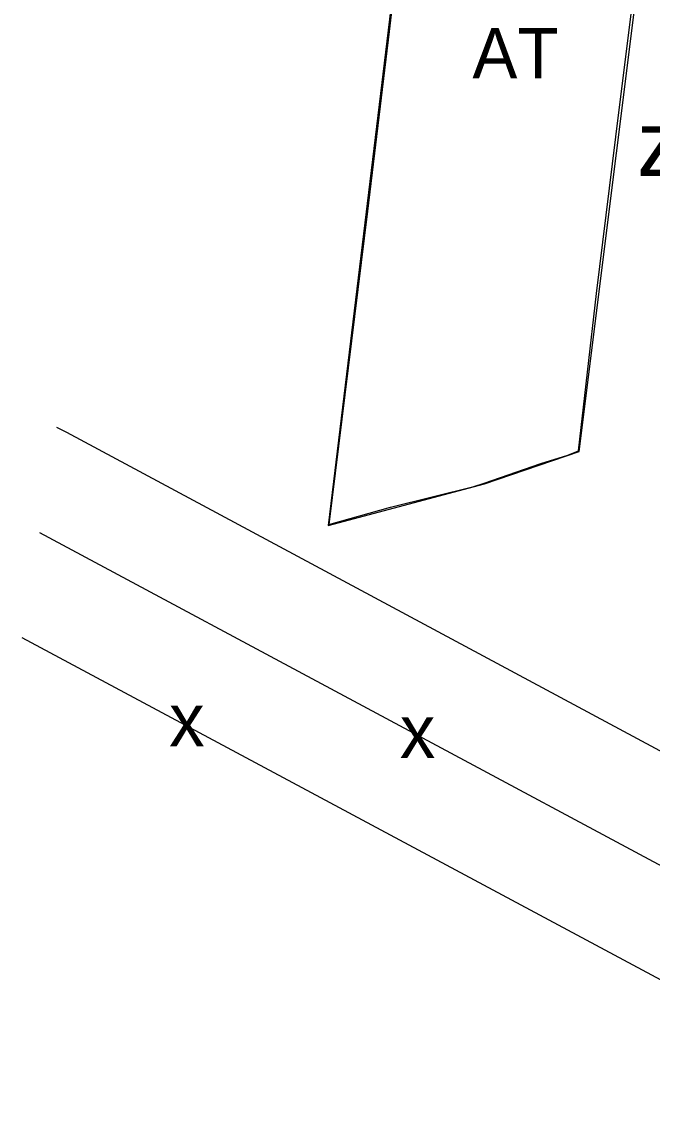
# Model space of a CAD drawing. Extents: x -555070 to -553076, y -1186731 to -1182766.
# Drawn here: x -555070.2 to -554895.6, y -1185500.5 to -1185196 of the extents above; entities that cross this region are included whole.
import ezdxf

# ---------------------------------------------------------------- set-up
doc = ezdxf.new("R2010")
doc.units = 0
for name, color, linetype in [('HRANICE_ZMENY_DO_KOO', 7, 'Continuous'), ('Level 10', 7, 'Continuous'), ('Level 29', 7, 'Continuous'), ('Level 59', 7, 'Continuous'), ('OBRYS_PLOCH', 7, 'Continuous'), ('stav_AT', 7, 'Continuous')]:
    doc.layers.add(name, color=color, linetype=linetype)

msp = doc.modelspace()

# ---------------------------------------------------------------- linework, layer by layer
at = {"layer": 'HRANICE_ZMENY_DO_KOO'}
msp.add_lwpolyline([(-555034.79, -1185063.53), (-555035.23, -1185086.95), (-554960.01, -1185120.64), (-554959.71, -1185123.38), (-554985.4, -1185335.61), (-554942.05, -1185324.03), (-554915.83, -1185315.05), (-554895.09, -1185149.59), (-554811.81, -1185186.74), (-554808.6, -1185185.28), (-554803.37, -1185165.66)], close=True, dxfattribs=at)
at = {"layer": 'Level 29'}
for points in [[(-554293.2, -1185505.39), (-554587.17, -1185457.18), (-554869.52, -1185410.99), (-555057.83, -1185309.87), (-555060.53, -1185308.42)], [(-555065.37, -1185337.55), (-554878.61, -1185437.76), (-554591.7, -1185484.82), (-554218.96, -1185545.93), (-553901.49, -1185597.94), (-553620.76, -1185643.99), (-553313.81, -1185694.25), (-553085.95, -1185731.63)], [(-555070.22, -1185366.68), (-555067.64, -1185368.06), (-554890.63, -1185462.96), (-554888.02, -1185464.13), (-554884.43, -1185465.07), (-554596.24, -1185512.45), (-554277.11, -1185564.77)]]:
    msp.add_lwpolyline(points, dxfattribs=at)
at = {"layer": 'OBRYS_PLOCH'}
for p, q in [((-554959.51, -1185123.38), (-554968.49, -1185198.61)), ((-554905.64, -1185227.88), (-554896.25, -1185151.54)), ((-554968.49, -1185198.61), (-554974.5, -1185248.5)), ((-554911.02, -1185271.3), (-554905.64, -1185227.88)), ((-554974.5, -1185248.5), (-554985.17, -1185335.34)), ((-554916.01, -1185314.9), (-554911.02, -1185271.3)), ((-554926.41, -1185318.46), (-554918.93, -1185316.1)), ((-554918.93, -1185316.1), (-554916.01, -1185314.9)), ((-554942.11, -1185323.84), (-554926.41, -1185318.46)), ((-554968.06, -1185330.5), (-554945.03, -1185324.82)), ((-554945.03, -1185324.82), (-554942.11, -1185323.84)), ((-554985.17, -1185335.34), (-554968.06, -1185330.5))]:
    msp.add_line(p, q, dxfattribs=at)
at = {"layer": 'stav_AT'}
for p, q in [((-554959.51, -1185123.38), (-554968.49, -1185198.61)), ((-554905.64, -1185227.88), (-554896.25, -1185151.54)), ((-554968.49, -1185198.61), (-554974.5, -1185248.5)), ((-554911.02, -1185271.3), (-554905.64, -1185227.88)), ((-554974.5, -1185248.5), (-554985.17, -1185335.34)), ((-554916.01, -1185314.9), (-554911.02, -1185271.3)), ((-554926.41, -1185318.46), (-554918.93, -1185316.1)), ((-554918.93, -1185316.1), (-554916.01, -1185314.9)), ((-554942.11, -1185323.84), (-554926.41, -1185318.46)), ((-554968.06, -1185330.5), (-554945.03, -1185324.82)), ((-554945.03, -1185324.82), (-554942.11, -1185323.84)), ((-554985.17, -1185335.34), (-554968.06, -1185330.5))]:
    msp.add_line(p, q, dxfattribs=at)

# ---------------------------------------------------------------- texts
at = {"layer": 'Level 10'}
msp.add_text('zm9f', height=18, dxfattribs=at).set_placement((-554899.8, -1185238.75))
at = {"layer": 'Level 29'}
for p in [(-555029.42, -1185396.81), (-554965.49, -1185400.04)]:
    msp.add_text('x', height=14.62, rotation=0.008, dxfattribs=at).set_placement(p)
at = {"layer": 'Level 59'}
msp.add_text('AT', height=14, dxfattribs=at).set_placement((-554945.42, -1185211.66))

doc.saveas('drawing.dxf')
